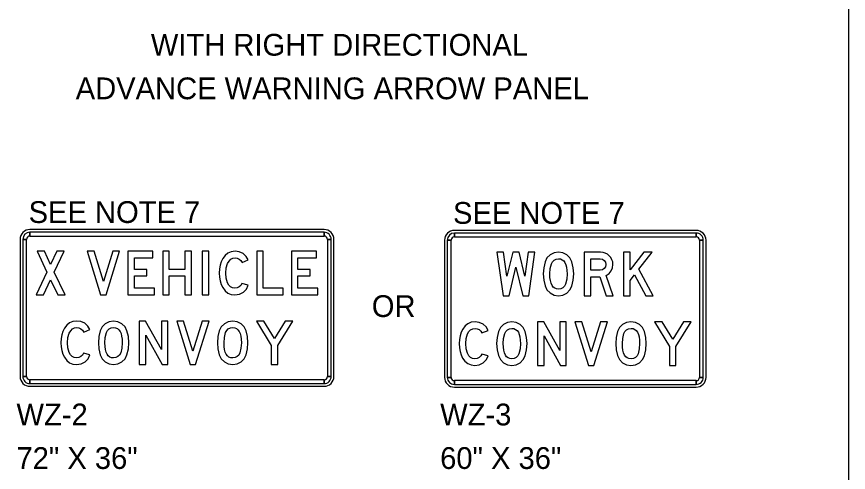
# Model space of a CAD drawing. Extents: x -747 to 834, y -5485 to -3577.
# Drawn here: x 87.5 to 316.6, y -4822.8 to -4697.2 of the extents above; entities that cross this region are included whole.
import ezdxf

# ---------------------------------------------------------------- set-up
doc = ezdxf.new("R2010")
doc.units = 0
doc.layers.add('Working Level 1', color=7, linetype='Continuous')

msp = doc.modelspace()

# ---------------------------------------------------------------- linework, layer by layer
at = {"layer": 'Working Level 1'}
for p, q in [((316.57, -4442.19), (316.57, -5484.51)), ((172.2, -4755.86), (91.2, -4755.86)), ((91.2, -4757.66), (91.2, -4756.61)), ((172.2, -4756.61), (172.2, -4757.66)), ((274.67, -4756.09), (208.07, -4756.09)), ((208.07, -4757.89), (208.07, -4756.84)), ((274.67, -4756.84), (274.67, -4757.89)), ((88.5, -4758.56), (88.5, -4796.36)), ((89.25, -4758.56), (90.3, -4758.56)), ((173.1, -4758.56), (174.15, -4758.56)), ((174.9, -4796.36), (174.9, -4758.56)), ((205.37, -4758.79), (205.37, -4796.59)), ((206.12, -4758.79), (207.17, -4758.79)), ((275.57, -4758.79), (276.62, -4758.79)), ((277.37, -4796.59), (277.37, -4758.79)), ((90.3, -4796.36), (89.25, -4796.36)), ((91.2, -4798.31), (91.2, -4797.26)), ((172.2, -4797.26), (172.2, -4798.31)), ((174.15, -4796.36), (173.1, -4796.36)), ((207.17, -4796.59), (206.12, -4796.59)), ((208.07, -4798.54), (208.07, -4797.49)), ((274.67, -4797.49), (274.67, -4798.54)), ((276.62, -4796.59), (275.57, -4796.59)), ((91.2, -4799.06), (172.2, -4799.06)), ((208.07, -4799.29), (274.67, -4799.29))]:
    msp.add_line(p, q, dxfattribs=at)
for points in [[(172.2, -4756.61), (91.2, -4756.61), (91.2, -4757.66), (172.2, -4757.66), (172.2, -4756.61)], [(274.67, -4756.84), (208.07, -4756.84), (208.07, -4757.89), (274.67, -4757.89), (274.67, -4756.84)], [(89.25, -4758.56), (89.25, -4796.36), (90.3, -4796.36), (90.3, -4758.56), (89.25, -4758.56)], [(174.15, -4796.36), (174.15, -4758.56), (173.1, -4758.56), (173.1, -4796.36), (174.15, -4796.36)], [(206.12, -4758.79), (206.12, -4796.59), (207.17, -4796.59), (207.17, -4758.79), (206.12, -4758.79)], [(276.62, -4796.59), (276.62, -4758.79), (275.57, -4758.79), (275.57, -4796.59), (276.62, -4796.59)], [(100.9, -4773.86), (97.91, -4767.58), (100.65, -4761.86), (98.65, -4761.86), (96.91, -4765.48), (95.18, -4761.86), (93.17, -4761.86), (95.9, -4767.59), (92.89, -4773.86), (94.9, -4773.86), (96.9, -4769.69), (98.89, -4773.86)], [(115.89, -4761.86), (113.99, -4761.86), (111.42, -4770.15), (108.85, -4761.86), (106.95, -4761.86), (110.67, -4773.86), (112.16, -4773.86)], [(125.46, -4772.05), (120.01, -4772.05), (120.01, -4768.65), (123.41, -4768.65), (123.41, -4766.84), (120.01, -4766.84), (120.01, -4763.67), (125.09, -4763.67), (125.09, -4761.86), (118.2, -4761.86), (118.2, -4773.86), (125.46, -4773.86)], [(135.69, -4773.86), (135.69, -4761.86), (133.88, -4761.86), (133.88, -4766.84), (129.58, -4766.84), (129.58, -4761.86), (127.76, -4761.86), (127.76, -4773.86), (129.58, -4773.86), (129.58, -4768.65), (133.88, -4768.65), (133.88, -4773.86)], [(140.45, -4773.86), (140.45, -4761.86), (138.64, -4761.86), (138.64, -4773.86)], [(151.34, -4771.2), (149.52, -4770.74), (149.25, -4771.26), (148.81, -4771.68), (148.25, -4771.96), (147.63, -4772.05), (147, -4771.95), (146.45, -4771.67), (146, -4771.19), (145.63, -4770.52), (145.26, -4769.29), (145.14, -4767.86), (145.26, -4766.42), (145.64, -4765.19), (146.02, -4764.53), (146.49, -4764.05), (147.04, -4763.77), (147.69, -4763.67), (148.28, -4763.76), (148.83, -4764), (149.29, -4764.4), (149.6, -4764.9), (151.34, -4764.22), (150.75, -4763.25), (149.89, -4762.5), (148.85, -4762.02), (147.71, -4761.86), (146.66, -4761.99), (145.74, -4762.36), (144.95, -4762.99), (144.29, -4763.86), (143.87, -4764.73), (143.57, -4765.68), (143.39, -4766.72), (143.33, -4767.85), (143.38, -4768.98), (143.56, -4770.02), (143.86, -4770.97), (144.28, -4771.84), (144.92, -4772.72), (145.7, -4773.35), (146.61, -4773.74), (147.65, -4773.86), (148.87, -4773.68), (149.97, -4773.12), (150.83, -4772.27)], [(160.9, -4773.86), (160.9, -4772.05), (155.45, -4772.05), (155.45, -4761.86), (153.64, -4761.86), (153.64, -4773.86)], [(170.46, -4772.05), (165.01, -4772.05), (165.01, -4768.65), (168.41, -4768.65), (168.41, -4766.84), (165.01, -4766.84), (165.01, -4763.67), (170.09, -4763.67), (170.09, -4761.86), (163.2, -4761.86), (163.2, -4773.86), (170.46, -4773.86)], [(230.23, -4762.1), (228.4, -4762.1), (227.48, -4768.67), (225.9, -4762.1), (224.14, -4762.1), (222.56, -4768.68), (221.64, -4762.1), (219.81, -4762.1), (221.49, -4774.09), (223.12, -4774.09), (225.02, -4766.2), (226.92, -4774.09), (228.55, -4774.09)], [(240.93, -4768.09), (240.81, -4766.38), (240.45, -4764.77), (239.91, -4763.69), (239.05, -4762.83), (237.96, -4762.28), (236.74, -4762.1), (235.52, -4762.28), (234.44, -4762.83), (233.58, -4763.69), (233.05, -4764.78), (232.68, -4766.39), (232.56, -4768.09), (232.68, -4769.79), (233.05, -4771.4), (233.58, -4772.49), (234.44, -4773.34), (235.52, -4773.91), (236.74, -4774.09), (237.96, -4773.91), (239.04, -4773.36), (239.89, -4772.5), (240.44, -4771.42), (240.81, -4769.81)], [(251.82, -4774.09), (249.92, -4768.49), (250.66, -4767.97), (251.24, -4767.25), (251.61, -4766.39), (251.73, -4765.47), (251.67, -4764.8), (251.48, -4764.18), (251.17, -4763.61), (250.73, -4763.09), (250.21, -4762.65), (249.63, -4762.34), (249.01, -4762.16), (248.34, -4762.1), (243.81, -4762.1), (243.81, -4774.09), (245.62, -4774.09), (245.62, -4768.89), (248.13, -4768.89), (249.91, -4774.09)], [(262.81, -4774.09), (258.91, -4766.78), (262.52, -4762.1), (260.24, -4762.1), (256.49, -4766.96), (256.49, -4762.1), (254.68, -4762.1), (254.68, -4774.09), (256.49, -4774.09), (256.49, -4769.92), (257.7, -4768.36), (260.76, -4774.09)], [(239.12, -4768.1), (239.02, -4769.55), (238.7, -4770.91), (238.41, -4771.47), (237.96, -4771.91), (237.39, -4772.19), (236.75, -4772.28), (236.19, -4772.22), (235.71, -4772.02), (235.3, -4771.7), (234.96, -4771.24), (234.7, -4770.65), (234.52, -4769.93), (234.4, -4769.08), (234.37, -4768.1), (234.47, -4766.64), (234.79, -4765.29), (235.08, -4764.73), (235.53, -4764.28), (236.1, -4764), (236.75, -4763.91), (237.31, -4763.97), (237.79, -4764.17), (238.19, -4764.5), (238.53, -4764.95), (238.79, -4765.54), (238.97, -4766.26), (239.08, -4767.12)], [(245.62, -4767.08), (245.62, -4763.91), (248.26, -4763.91), (248.83, -4764.03), (249.32, -4764.38), (249.65, -4764.89), (249.77, -4765.49), (249.65, -4766.1), (249.32, -4766.61), (248.83, -4766.96), (248.26, -4767.08)], [(107.74, -4790.4), (105.93, -4789.94), (105.66, -4790.46), (105.22, -4790.88), (104.66, -4791.16), (104.03, -4791.25), (103.4, -4791.15), (102.86, -4790.87), (102.4, -4790.39), (102.04, -4789.72), (101.67, -4788.49), (101.55, -4787.06), (101.67, -4785.62), (102.05, -4784.39), (102.43, -4783.73), (102.9, -4783.25), (103.45, -4782.97), (104.09, -4782.87), (104.69, -4782.96), (105.24, -4783.2), (105.69, -4783.6), (106, -4784.1), (107.74, -4783.42), (107.16, -4782.45), (106.3, -4781.7), (105.26, -4781.22), (104.12, -4781.06), (103.06, -4781.19), (102.14, -4781.56), (101.35, -4782.19), (100.7, -4783.06), (100.28, -4783.93), (99.97, -4784.88), (99.79, -4785.92), (99.73, -4787.05), (99.79, -4788.18), (99.97, -4789.22), (100.27, -4790.17), (100.69, -4791.04), (101.33, -4791.92), (102.11, -4792.55), (103.02, -4792.94), (104.06, -4793.06), (105.28, -4792.88), (106.38, -4792.32), (107.23, -4791.47)], [(118.42, -4787.05), (118.3, -4785.34), (117.93, -4783.74), (117.39, -4782.66), (116.53, -4781.8), (115.45, -4781.25), (114.23, -4781.06), (113.01, -4781.25), (111.93, -4781.8), (111.07, -4782.66), (110.53, -4783.75), (110.17, -4785.35), (110.05, -4787.05), (110.17, -4788.75), (110.53, -4790.36), (111.07, -4791.45), (111.93, -4792.31), (113.01, -4792.87), (114.23, -4793.06), (115.44, -4792.88), (116.53, -4792.32), (117.38, -4791.47), (117.92, -4790.38), (118.3, -4788.77)], [(129.22, -4793.06), (129.22, -4781.06), (127.41, -4781.06), (127.41, -4788.95), (123.04, -4781.06), (121.3, -4781.06), (121.3, -4793.06), (123.11, -4793.06), (123.11, -4784.92), (127.62, -4793.06)], [(140.54, -4781.06), (138.65, -4781.06), (136.07, -4789.35), (133.5, -4781.06), (131.61, -4781.06), (135.33, -4793.06), (136.82, -4793.06)], [(151.23, -4787.05), (151.11, -4785.34), (150.75, -4783.74), (150.21, -4782.66), (149.35, -4781.8), (148.26, -4781.25), (147.04, -4781.06), (145.82, -4781.25), (144.74, -4781.8), (143.88, -4782.66), (143.35, -4783.75), (142.98, -4785.35), (142.86, -4787.05), (142.98, -4788.75), (143.35, -4790.36), (143.88, -4791.45), (144.74, -4792.31), (145.82, -4792.87), (147.04, -4793.06), (148.26, -4792.88), (149.34, -4792.32), (150.19, -4791.47), (150.74, -4790.38), (151.11, -4788.77)], [(163.6, -4781.06), (161.48, -4781.06), (158.53, -4785.85), (155.65, -4781.06), (153.55, -4781.06), (157.62, -4787.8), (157.62, -4793.06), (159.43, -4793.06), (159.43, -4787.85)], [(217.41, -4790.63), (215.6, -4790.17), (215.33, -4790.7), (214.89, -4791.11), (214.33, -4791.39), (213.7, -4791.48), (213.07, -4791.39), (212.53, -4791.1), (212.07, -4790.62), (211.71, -4789.95), (211.33, -4788.72), (211.21, -4787.29), (211.34, -4785.86), (211.72, -4784.62), (212.1, -4783.96), (212.56, -4783.49), (213.12, -4783.2), (213.76, -4783.11), (214.36, -4783.19), (214.91, -4783.44), (215.36, -4783.83), (215.67, -4784.33), (217.41, -4783.65), (216.82, -4782.69), (215.97, -4781.94), (214.93, -4781.46), (213.79, -4781.29), (212.73, -4781.42), (211.81, -4781.8), (211.02, -4782.42), (210.37, -4783.3), (209.94, -4784.16), (209.64, -4785.11), (209.46, -4786.16), (209.4, -4787.29), (209.46, -4788.42), (209.64, -4789.46), (209.94, -4790.41), (210.36, -4791.27), (211, -4792.16), (211.78, -4792.79), (212.69, -4793.17), (213.73, -4793.29), (214.95, -4793.11), (216.05, -4792.55), (216.9, -4791.7)], [(228.09, -4787.29), (227.97, -4785.57), (227.6, -4783.97), (227.06, -4782.89), (226.2, -4782.03), (225.12, -4781.48), (223.9, -4781.29), (222.68, -4781.48), (221.6, -4782.03), (220.74, -4782.89), (220.2, -4783.98), (219.84, -4785.59), (219.71, -4787.29), (219.84, -4788.99), (220.2, -4790.59), (220.74, -4791.68), (221.6, -4792.54), (222.68, -4793.11), (223.9, -4793.29), (225.11, -4793.11), (226.2, -4792.55), (227.05, -4791.7), (227.59, -4790.62), (227.96, -4789.01)], [(238.89, -4793.29), (238.89, -4781.29), (237.08, -4781.29), (237.08, -4789.18), (232.7, -4781.29), (230.96, -4781.29), (230.96, -4793.29), (232.78, -4793.29), (232.78, -4785.15), (237.29, -4793.29)], [(250.21, -4781.29), (248.32, -4781.29), (245.74, -4789.59), (243.17, -4781.29), (241.28, -4781.29), (244.99, -4793.29), (246.48, -4793.29)], [(260.9, -4787.29), (260.78, -4785.57), (260.41, -4783.97), (259.87, -4782.89), (259.01, -4782.03), (257.93, -4781.48), (256.71, -4781.29), (255.49, -4781.48), (254.41, -4782.03), (253.55, -4782.89), (253.01, -4783.98), (252.65, -4785.59), (252.53, -4787.29), (252.65, -4788.99), (253.01, -4790.59), (253.55, -4791.68), (254.41, -4792.54), (255.49, -4793.11), (256.71, -4793.29), (257.92, -4793.11), (259.01, -4792.55), (259.86, -4791.7), (260.4, -4790.62), (260.77, -4789.01)], [(273.27, -4781.29), (271.14, -4781.29), (268.2, -4786.08), (265.32, -4781.29), (263.21, -4781.29), (267.29, -4788.04), (267.29, -4793.29), (269.1, -4793.29), (269.1, -4788.09)], [(116.61, -4787.06), (116.51, -4788.52), (116.19, -4789.87), (115.9, -4790.44), (115.45, -4790.88), (114.88, -4791.16), (114.24, -4791.25), (113.68, -4791.19), (113.19, -4790.99), (112.78, -4790.66), (112.45, -4790.2), (112.19, -4789.61), (112.01, -4788.89), (111.89, -4788.04), (111.86, -4787.06), (111.96, -4785.61), (112.28, -4784.26), (112.57, -4783.69), (113.02, -4783.25), (113.59, -4782.97), (114.24, -4782.87), (114.79, -4782.94), (115.27, -4783.13), (115.68, -4783.46), (116.02, -4783.92), (116.28, -4784.51), (116.46, -4785.23), (116.57, -4786.08)], [(149.42, -4787.06), (149.32, -4788.52), (149, -4789.87), (148.71, -4790.44), (148.26, -4790.88), (147.69, -4791.16), (147.05, -4791.25), (146.49, -4791.19), (146.01, -4790.99), (145.6, -4790.66), (145.26, -4790.2), (145, -4789.61), (144.82, -4788.89), (144.7, -4788.04), (144.67, -4787.06), (144.78, -4785.61), (145.09, -4784.26), (145.38, -4783.69), (145.83, -4783.25), (146.4, -4782.97), (147.05, -4782.87), (147.61, -4782.94), (148.09, -4783.13), (148.49, -4783.46), (148.83, -4783.92), (149.09, -4784.51), (149.27, -4785.23), (149.38, -4786.08)], [(226.28, -4787.29), (226.17, -4788.75), (225.86, -4790.11), (225.57, -4790.67), (225.12, -4791.11), (224.55, -4791.39), (223.91, -4791.48), (223.35, -4791.42), (222.86, -4791.22), (222.45, -4790.89), (222.12, -4790.44), (221.86, -4789.85), (221.67, -4789.13), (221.56, -4788.28), (221.53, -4787.29), (221.63, -4785.84), (221.95, -4784.49), (222.24, -4783.93), (222.69, -4783.48), (223.26, -4783.2), (223.91, -4783.11), (224.46, -4783.17), (224.94, -4783.37), (225.35, -4783.7), (225.69, -4784.15), (225.94, -4784.74), (226.13, -4785.46), (226.24, -4786.31)], [(259.09, -4787.29), (258.98, -4788.75), (258.67, -4790.11), (258.38, -4790.67), (257.93, -4791.11), (257.36, -4791.39), (256.72, -4791.48), (256.16, -4791.42), (255.67, -4791.22), (255.26, -4790.89), (254.93, -4790.44), (254.67, -4789.85), (254.49, -4789.13), (254.37, -4788.28), (254.34, -4787.29), (254.44, -4785.84), (254.76, -4784.49), (255.05, -4783.93), (255.5, -4783.48), (256.07, -4783.2), (256.72, -4783.11), (257.27, -4783.17), (257.75, -4783.37), (258.16, -4783.7), (258.5, -4784.15), (258.76, -4784.74), (258.94, -4785.46), (259.05, -4786.31)], [(91.2, -4798.31), (172.2, -4798.31), (172.2, -4797.26), (91.2, -4797.26), (91.2, -4798.31)], [(208.07, -4798.54), (274.67, -4798.54), (274.67, -4797.49), (208.07, -4797.49), (208.07, -4798.54)]]:
    msp.add_lwpolyline(points, close=True, dxfattribs=at)
for centre, radius, start, end in [((91.2, -4758.56), 2.7, 90.0002, 179.9998), ((91.2, -4758.56), 1.95, 90.0002, 179.9998), ((172.2, -4758.56), 2.7, 0, 90.0002), ((172.2, -4758.56), 1.95, 0, 90.0002), ((208.07, -4758.79), 2.7, 90.0002, 179.9998), ((208.07, -4758.79), 1.95, 90.0002, 179.9998), ((274.67, -4758.79), 2.7, 0, 90.0002), ((274.67, -4758.79), 1.95, 0, 90.0002), ((91.2, -4758.56), 0.9, 90.0002, 179.9998), ((172.2, -4758.56), 0.9, 0, 90.0002), ((208.07, -4758.79), 0.9, 90.0002, 179.9998), ((274.67, -4758.79), 0.9, 0, 90.0002), ((91.2, -4796.36), 2.7, 179.9998, 270.0001), ((91.2, -4796.36), 1.95, 179.9998, 270.0001), ((91.2, -4796.36), 0.9, 179.9998, 270.0001), ((172.2, -4796.36), 2.7, 270.0001, 0.0003), ((172.2, -4796.36), 1.95, 270.0001, 0.0003), ((172.2, -4796.36), 0.9, 270.0001, 0.0003), ((208.07, -4796.59), 2.7, 179.9998, 270.0001), ((208.07, -4796.59), 1.95, 179.9998, 270.0001), ((208.07, -4796.59), 0.9, 179.9998, 270.0001), ((274.67, -4796.59), 2.7, 270.0001, 0.0003), ((274.67, -4796.59), 1.95, 270.0001, 0.0003), ((274.67, -4796.59), 0.9, 270.0001, 0.0003)]:
    msp.add_arc(centre, radius, start, end, dxfattribs=at)

# ---------------------------------------------------------------- texts
for s, p in [('WITH RIGHT DIRECTIONAL', (124.5, -4707.96)), ('ADVANCE WARNING ARROW PANEL', (103.81, -4719.96)), ('SEE NOTE 7 ', (90.84, -4754.05)), ('SEE NOTE 7 ', (207.71, -4754.29))]:
    msp.add_text(s, height=6, dxfattribs=at).set_placement(p)
for s, p in [('OR', (185.34, -4779.96)), ('WZ-2', (87.5, -4809.82)), ('WZ-3', (204.16, -4809.82)), ('72" X 36"', (87.5, -4821.82)), ('60" X 36"', (204.16, -4821.82))]:
    msp.add_text(s, height=6, rotation=0, dxfattribs=at).set_placement(p)

doc.saveas('drawing.dxf')
